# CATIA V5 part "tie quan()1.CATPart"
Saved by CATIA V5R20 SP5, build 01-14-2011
Part number: 外框
Bounding box of the stored display mesh (mm): x -152.63 to 152.63, y -152.63 to 152.63, z -0.505 to 111
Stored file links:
  E:\姜浩然03.08\创意作品\tie quan()1.CATPart
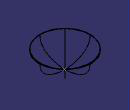
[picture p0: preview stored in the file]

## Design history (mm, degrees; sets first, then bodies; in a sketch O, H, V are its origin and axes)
Body1 (main body)
  Sketch1 on xy-plane, origin (0, 0, 0), H (1, 0, 0), V (0, 1, 0)
    circle A1 centre (0, 0) radius 5
  Pad1: profile Sketch1, direction (0, 0, 1), length 0.5, mirrored extent
  Plane1: type Offset, RefPlane zx-plane, Offset 5, reversed
  Point1: type OnPlane, Support Plane1, H 0, V 0, Direction (-1, 0, 0)
  Circle1: type CtrRad, Start 0, End 180, Center Point1, Support Plane1, Radius 0.5, FirstDirection (-1, 0, 0)
  Sketch2 on yz-plane, origin (0, 0, 0), H (0, 1, 0), V (0, 0, 1)
    spline S1 through (-4.955, 0) (-152.1268, 105.2207) (-152.1268, 109.4858)
    point P1 (-4.955, 0)
    coincidence: P1 H
  Rib1: profile Circle1, centre curve Sketch2
  CircPattern1: of the body so far, instances 8, angular step 45, axis from end face of Pad1
Body2
  Plane2: type Offset, RefPlane xy-plane, Offset 110
  Sketch3 on Plane2, origin (0, 0, 110), H (1, 0, 0), V (0, 1, 0)
    circle A1 centre (0, 0) radius 151.634
  Pad2: profile Sketch3, direction (0, 0, 1), length 1, mirrored extent
  Sketch4 on end face of Pad2, origin (0, 0, 111), H (1, 0, 0), V (0, 1, 0)
    point P1 (0, 0)
  Hole1: placed by Sketch4, at (0, 0, 111) direction (0, 0, -1), diameter 300, through (limit type 6)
